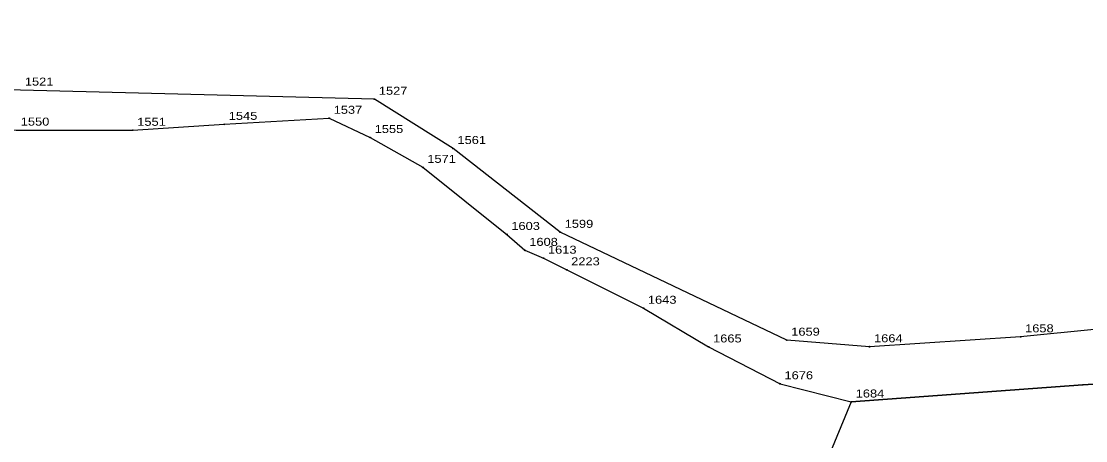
# Model space of a CAD drawing. Extents: x 4640203 to 4641683, y 5358965 to 5360242.
# Drawn here: x 4640576.9 to 4640696.6, y 5360016 to 5360063.1 of the extents above; entities that cross this region are included whole.
import ezdxf

# ---------------------------------------------------------------- set-up
doc = ezdxf.new("R2010")
doc.units = 0
doc.header["$LTSCALE"] = 0.36
for name, color, linetype, lineweight in [('25', 7, 'Continuous', 25), ('27', 7, 'Continuous', 25), ('8', 7, 'Continuous', 25)]:
    doc.layers.add(name, color=color, linetype=linetype, lineweight=lineweight)

msp = doc.modelspace()

# ---------------------------------------------------------------- linework, layer by layer
at = {"layer": '25'}
for points in [[(4640827.98, 5360035.67), (4640811.29, 5360033.86), (4640797.5, 5360032.27), (4640780.61, 5360030.86), (4640766.2, 5360031.76), (4640761.8, 5360032.53), (4640757.5, 5360032.6), (4640746.4, 5360032.42), (4640722.91, 5360030.97), (4640707.01, 5360029.39), (4640689.33, 5360027.64), (4640672.34, 5360026.52), (4640663.03, 5360027.26), (4640637.55, 5360039.39), (4640625.49, 5360048.81), (4640616.65, 5360054.35), (4640576.84, 5360055.38)], [(4640576.38, 5360050.88), (4640589.48, 5360050.86), (4640599.77, 5360051.53), (4640611.57, 5360052.21), (4640616.18, 5360050.05), (4640622.1, 5360046.69), (4640631.55, 5360039.15), (4640633.57, 5360037.36), (4640635.67, 5360036.48), (4640638.28, 5360035.17), (4640646.91, 5360030.85), (4640654.24, 5360026.5), (4640662.27, 5360022.36), (4640670.28, 5360020.31), (4640696.32, 5360022.23), (4640698.67, 5360022.4)]]:
    msp.add_lwpolyline(points, dxfattribs=at)
at = {"layer": '27'}
for points in [[(4640707.01, 5360029.39), (4640689.33, 5360027.64), (4640672.34, 5360026.52), (4640663.03, 5360027.26), (4640637.55, 5360039.39), (4640625.49, 5360048.81), (4640616.65, 5360054.35), (4640576.84, 5360055.38), (4640560.72, 5360055.73), (4640536.93, 5360058.21), (4640523.61, 5360059.87), (4640507.4, 5360062.51), (4640473.7, 5360062.18), (4640456.6, 5360062.07), (4640436.47, 5360062.36), (4640433.09, 5360063.11), (4640421.87, 5360051.33)], [(4640545.16, 5360053.77), (4640564.27, 5360051.69), (4640568.27, 5360051.42), (4640576.38, 5360050.88), (4640589.48, 5360050.86), (4640599.77, 5360051.53), (4640611.57, 5360052.21), (4640616.18, 5360050.05), (4640622.1, 5360046.69), (4640631.55, 5360039.15), (4640633.57, 5360037.36), (4640635.67, 5360036.48), (4640638.28, 5360035.17), (4640646.91, 5360030.85), (4640654.24, 5360026.5), (4640662.27, 5360022.36), (4640670.28, 5360020.31)], [(4640904.69, 5360018.38), (4640888.57, 5360022.18), (4640879.12, 5359986.05), (4640856.44, 5359988.67), (4640836.58, 5359990.96), (4640835.87, 5360009.69), (4640835.91, 5360014.37), (4640835.89, 5360016.46), (4640835.72, 5360033.46), (4640834.19, 5360033.52), (4640828.19, 5360033.58), (4640810.42, 5360029.96), (4640782.83, 5360028.37), (4640764.33, 5360028.49), (4640759.93, 5360028.52), (4640747.03, 5360028.43), (4640735.13, 5360027.68), (4640723.74, 5360026.97), (4640703.76, 5360023.34), (4640698.67, 5360022.4), (4640696.32, 5360022.23), (4640670.28, 5360020.31), (4640655.62, 5359984.88), (4640641.2, 5359946.4)]]:
    msp.add_lwpolyline(points, dxfattribs=at)
at = {"layer": '8'}
for centre in [(4640616.65, 5360054.35), (4640599.77, 5360051.53), (4640611.57, 5360052.21), (4640589.48, 5360050.86), (4640616.18, 5360050.05), (4640625.49, 5360048.81), (4640622.1, 5360046.69), (4640631.55, 5360039.15), (4640637.55, 5360039.39), (4640633.57, 5360037.36), (4640635.67, 5360036.48), (4640638.28, 5360035.17), (4640646.91, 5360030.85), (4640663.03, 5360027.26), (4640689.33, 5360027.64), (4640654.24, 5360026.5), (4640672.34, 5360026.52), (4640662.27, 5360022.36), (4640696.32, 5360022.23), (4640670.28, 5360020.31)]:
    msp.add_circle(centre, 0.045, dxfattribs=at)

# ---------------------------------------------------------------- texts
at = {"layer": '8', "width": 1.2}
for s, p in [('1521', (4640577.34, 5360055.88)), ('1527', (4640617.15, 5360054.85)), ('1537', (4640612.07, 5360052.71)), ('1545', (4640600.27, 5360052.03)), ('1550', (4640576.88, 5360051.38)), ('1551', (4640589.98, 5360051.36)), ('1555', (4640616.68, 5360050.55)), ('1561', (4640625.99, 5360049.31)), ('1571', (4640622.6, 5360047.19)), ('1603', (4640632.05, 5360039.65)), ('1599', (4640638.05, 5360039.89)), ('1608', (4640634.07, 5360037.86)), ('1613', (4640636.17, 5360036.98)), ('2223', (4640638.78, 5360035.67)), ('1643', (4640647.41, 5360031.35)), ('1659', (4640663.53, 5360027.76)), ('1658', (4640689.83, 5360028.14)), ('1665', (4640654.74, 5360027)), ('1664', (4640672.84, 5360027.02)), ('1676', (4640662.77, 5360022.86)), ('1684', (4640670.78, 5360020.81))]:
    msp.add_text(s, height=0.9, dxfattribs=at).set_placement(p)

doc.saveas('drawing.dxf')
